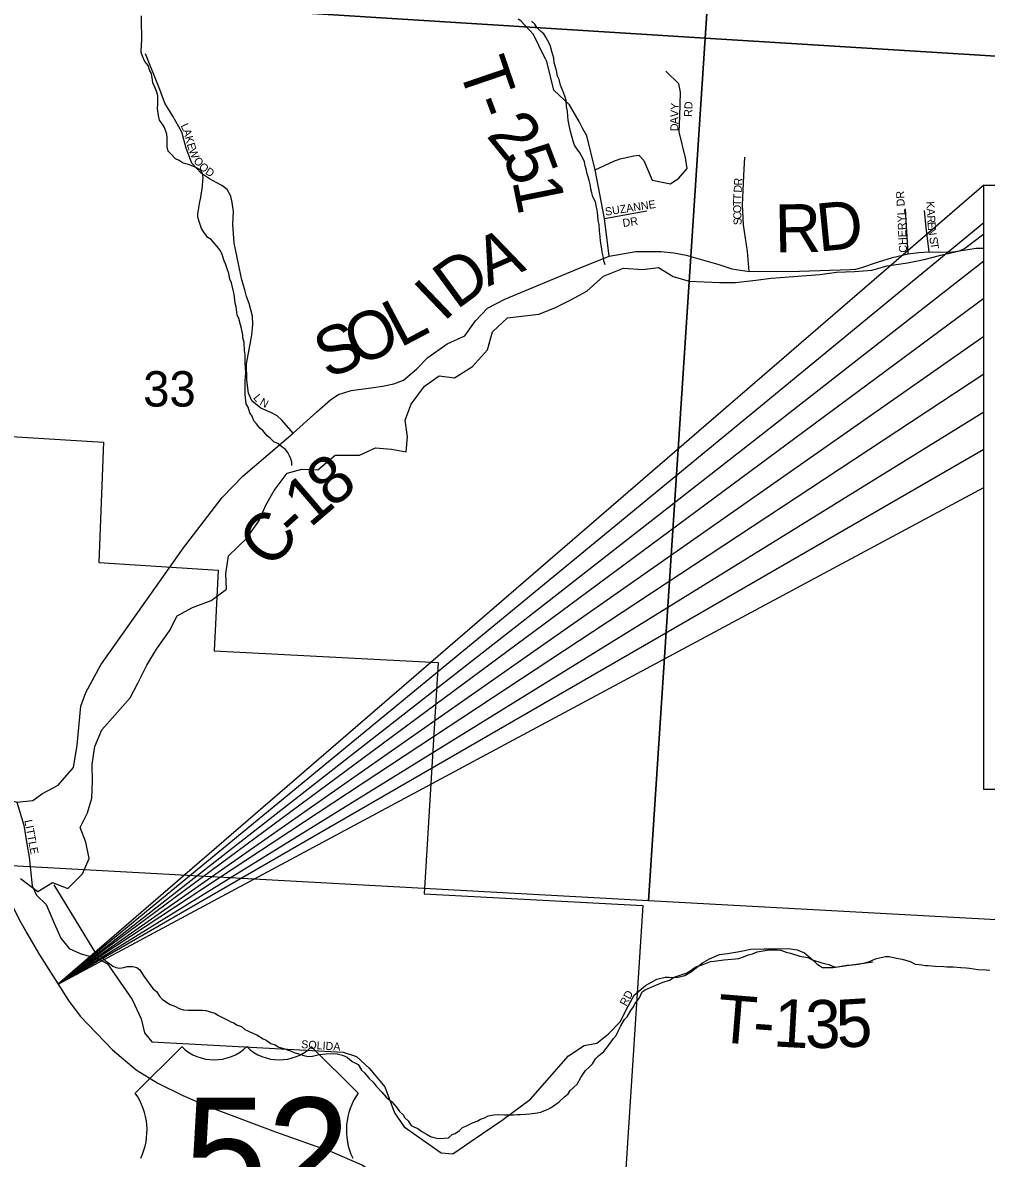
# Model space of a CAD drawing. Extents: x 0 to 34, y 0 to 22.
# Drawn here: x 4.916 to 6.056, y 15.623 to 16.966 of the extents above; entities that cross this region are included whole.
import ezdxf

# ---------------------------------------------------------------- set-up
doc = ezdxf.new("R2010")
doc.units = 0
for name, color, linetype in [('GM_X_City_Street', 7, 'Continuous'), ('GM_X_City_Street_Text', 7, 'Continuous'), ('GM_X_Corporation', 7, 'Continuous'), ('GM_X_County_Road', 7, 'Continuous'), ('GM_X_County_Road_Text', 7, 'Continuous'), ('GM_X_Minor_River', 7, 'Continuous'), ('GM_X_Section', 7, 'Continuous'), ('GM_X_Section_Text', 7, 'Continuous'), ('GM_X_Township_Road', 7, 'Continuous'), ('GM_X_Township_Road_Text', 7, 'Continuous'), ('GM_X_Township_Subdivision', 7, 'Continuous'), ('GM_X_Township_Subdivision_Text', 7, 'Continuous'), ('GM_X_US_Location', 7, 'Continuous'), ('GM_X_US_Route', 7, 'Continuous'), ('GM_X_US_Shield', 7, 'Continuous'), ('SH_Text', 7, 'Continuous')]:
    doc.layers.add(name, color=color, linetype=linetype)

msp = doc.modelspace()

# ---------------------------------------------------------------- linework, layer by layer
at = {"layer": 'GM_X_City_Street'}
for points in [[(4.7142, 16.2859), (4.7289, 16.2719), (4.7564, 16.2394), (4.784, 16.21), (4.7944, 16.1975), (4.7992, 16.1905), (4.8021, 16.1756), (4.8137, 16.1619), (4.8296, 16.149), (4.8455, 16.13), (4.8663, 16.0699), (4.8842, 16.0666), (4.8936, 16.0489), (4.909, 16.0441), (4.9279, 16.0462), (4.9395, 16.0544), (4.958, 16.0642), (4.9762, 16.0851), (4.9804, 16.1117), (4.9849, 16.1577), (4.9906, 16.174), (5.0084, 16.2067), (5.094, 16.3278), (5.0961, 16.3307)], [(4.909, 16.0441), (4.9172, 16.0171), (4.9208, 15.9949), (4.9237, 15.9791), (4.9251, 15.9641), (4.9273, 15.9454), (4.9323, 15.934), (4.9438, 15.9232), (4.9531, 15.901), (4.961, 15.8831), (4.971, 15.8709), (4.9839, 15.8651), (5.0054, 15.8587), (5.0162, 15.853), (5.0276, 15.8365), (5.0456, 15.8107), (5.0563, 15.7877), (5.06, 15.7711), (5.0686, 15.7607), (5.295, 15.7483), (5.3108, 15.7433), (5.3259, 15.7296), (5.3445, 15.7074), (5.356, 15.6766), (5.3675, 15.6601), (5.4111, 15.6292), (5.4248, 15.628), (5.4602, 15.6523), (5.4832, 15.6681), (5.517, 15.6927), (5.562, 15.7439), (5.5805, 15.7561), (5.5953, 15.7592), (5.6091, 15.7699), (5.6229, 15.7843), (5.6324, 15.8029), (5.6394, 15.8157), (5.6531, 15.8273), (5.6664, 15.8348), (5.6762, 15.8373), (5.6806, 15.8371)]]:
    msp.add_lwpolyline(points, dxfattribs=at)
at = {"layer": 'GM_X_Corporation'}
msp.add_lwpolyline([(4.6006, 16.4954), (5.0117, 16.4703), (5.0062, 16.3278), (5.1471, 16.3189), (5.1425, 16.2232), (5.4078, 16.2093), (5.3912, 15.9359), (5.65, 15.9221), (5.5944, 15.0667), (5.4633, 15.0824), (5.3998, 14.8756), (5.3493, 14.8892), (5.1229, 14.9601), (4.9836, 14.9934), (4.9409, 15.0109), (4.8087, 15.0697)], dxfattribs=at)
at = {"layer": 'GM_X_County_Road'}
for points in [[(5.6099, 16.6903), (5.6417, 16.6958), (5.6577, 16.6958), (5.6711, 16.6956), (5.6866, 16.694), (5.7011, 16.6914), (5.7397, 16.6804), (5.7552, 16.6752), (5.7755, 16.6719), (5.8351, 16.6725), (5.895, 16.6746), (5.9018, 16.675), (5.9089, 16.677), (5.9275, 16.683), (5.9453, 16.6887), (5.9638, 16.693), (5.9763, 16.6947), (5.9887, 16.6952), (6.0026, 16.695), (6.0167, 16.6954), (6.0244, 16.6964), (6.0304, 16.6993), (6.0532, 16.7167)], [(5.0961, 16.3307), (5.105, 16.3434), (5.152, 16.4048), (5.177, 16.4304), (5.2362, 16.4808), (5.2642, 16.5059), (5.2804, 16.5205), (5.2896, 16.5264), (5.3047, 16.5313), (5.3312, 16.5349), (5.3419, 16.5364), (5.3553, 16.5393), (5.3667, 16.5434), (5.3823, 16.5569), (5.3952, 16.5705), (5.4183, 16.5865), (5.4392, 16.596), (5.4517, 16.6138), (5.4661, 16.6286), (5.4865, 16.6393), (5.5735, 16.6756), (5.6099, 16.6903)]]:
    msp.add_lwpolyline(points, dxfattribs=at)
at = {"layer": 'GM_X_Minor_River'}
for points in [[(5.2344, 16.4426), (5.2345, 16.4464), (5.2334, 16.4506), (5.2316, 16.4541), (5.2298, 16.4579), (5.2268, 16.4614), (5.2227, 16.4645), (5.2178, 16.4684), (5.2133, 16.4707), (5.2089, 16.475), (5.2051, 16.4777), (5.2003, 16.4839), (5.1966, 16.4866), (5.1925, 16.492), (5.1895, 16.4954), (5.1873, 16.5008), (5.1848, 16.5047), (5.1826, 16.5115), (5.1804, 16.5154), (5.1791, 16.5264), (5.1794, 16.5431), (5.1798, 16.5469), (5.1799, 16.5534), (5.1796, 16.5572), (5.1794, 16.5644), (5.1791, 16.5686), (5.1792, 16.5739), (5.1785, 16.5785), (5.1779, 16.588), (5.1765, 16.5938), (5.1765, 16.5972), (5.1748, 16.6048), (5.1737, 16.609), (5.1719, 16.6166), (5.1697, 16.6209), (5.1684, 16.6304), (5.1673, 16.6346), (5.167, 16.638), (5.166, 16.6453), (5.165, 16.6502), (5.1632, 16.6586), (5.161, 16.6632), (5.16, 16.6697), (5.1578, 16.6751), (5.156, 16.6812), (5.1542, 16.6846), (5.1521, 16.6923), (5.1499, 16.6965), (5.1476, 16.6999), (5.1439, 16.7046), (5.1391, 16.71), (5.135, 16.7123), (5.1309, 16.7173), (5.1276, 16.7231), (5.1251, 16.73), (5.1233, 16.7365), (5.1233, 16.7403), (5.1242, 16.7475), (5.1255, 16.7547), (5.1267, 16.7596), (5.1272, 16.7634), (5.1284, 16.7695), (5.1289, 16.7744), (5.1293, 16.779), (5.1294, 16.7835), (5.1287, 16.7881), (5.1265, 16.7923), (5.1194, 16.7959), (5.1122, 16.7986), (5.1058, 16.8003), (5.101, 16.8034), (5.0968, 16.8054), (5.0913, 16.8112), (5.0879, 16.8143), (5.0869, 16.8196), (5.087, 16.8302), (5.0864, 16.8344), (5.0838, 16.8425), (5.0813, 16.8463), (5.0779, 16.8513), (5.0765, 16.8567), (5.0755, 16.865), (5.076, 16.8696), (5.0758, 16.8799), (5.0747, 16.8841), (5.0729, 16.8894), (5.07, 16.8952), (5.0697, 16.8986), (5.0683, 16.9062), (5.0665, 16.9097), (5.0643, 16.9158), (5.0606, 16.9204), (5.0577, 16.9269), (5.0562, 16.9312), (5.0564, 16.941), (5.0569, 16.9456), (5.057, 16.9551), (5.0564, 16.9608), (5.0566, 16.9745)], [(5.6053, 16.68), (5.6038, 16.6846), (5.6031, 16.6885), (5.6017, 16.6949), (5.6014, 16.6987), (5.6004, 16.7037), (5.5997, 16.7079), (5.5994, 16.7136), (5.5984, 16.7197), (5.5981, 16.7277), (5.5971, 16.7323), (5.5964, 16.7384), (5.5958, 16.7448), (5.5947, 16.7502), (5.5937, 16.7544), (5.5908, 16.7605), (5.5893, 16.7651), (5.5883, 16.7697), (5.5879, 16.7735), (5.5862, 16.7796), (5.5851, 16.7842), (5.584, 16.7876), (5.5826, 16.7934), (5.5815, 16.7972), (5.5809, 16.8018), (5.5794, 16.8056), (5.5772, 16.809), (5.5754, 16.8125), (5.572, 16.8167), (5.5691, 16.8217), (5.5673, 16.8263), (5.5644, 16.8378), (5.5627, 16.8454), (5.5616, 16.8511), (5.561, 16.8557), (5.5607, 16.8614), (5.5593, 16.8675), (5.559, 16.8748), (5.558, 16.8782), (5.5558, 16.8839), (5.554, 16.8885), (5.5525, 16.8924), (5.5507, 16.8992), (5.5489, 16.9031), (5.5475, 16.9099), (5.5465, 16.9138), (5.545, 16.9191), (5.5444, 16.9244), (5.5422, 16.9325), (5.5401, 16.9397), (5.5368, 16.9459), (5.535, 16.9493), (5.5327, 16.9532), (5.529, 16.9559), (5.5245, 16.9609), (5.522, 16.9647), (5.5182, 16.9682)], [(4.9987, 16.0689), (4.998, 16.0886), (5.0012, 16.1099), (5.0096, 16.1296), (5.0248, 16.147), (5.043, 16.1675), (5.0522, 16.1849), (5.0629, 16.2062), (5.0743, 16.2251), (5.0896, 16.2471), (5.0987, 16.2646), (5.117, 16.2744), (5.139, 16.2827), (5.1572, 16.2963), (5.1565, 16.3145), (5.1596, 16.3358), (5.1809, 16.3562), (5.1954, 16.3767), (5.2038, 16.3957), (5.2137, 16.4131), (5.229, 16.4336), (5.2464, 16.4381), (5.2653, 16.4373), (5.2858, 16.4547), (5.3146, 16.4546), (5.3336, 16.4636), (5.3525, 16.462), (5.3699, 16.4589), (5.3715, 16.4764), (5.3686, 16.4962), (5.3755, 16.5152), (5.3915, 16.5364), (5.4089, 16.5485), (5.4271, 16.5461), (5.4484, 16.5597), (5.4659, 16.5794), (5.472, 16.6007), (5.4895, 16.6174), (5.5266, 16.6218), (5.5456, 16.6293), (5.5646, 16.6384), (5.5835, 16.6489), (5.6033, 16.6664), (5.6268, 16.6762), (5.6495, 16.6746), (5.6685, 16.6768), (5.6859, 16.6661), (5.7048, 16.6607), (5.7222, 16.6598), (5.7404, 16.659), (5.7593, 16.659), (5.7836, 16.6619), (5.8017, 16.6641), (5.823, 16.6656), (5.8593, 16.6685), (5.879, 16.6714), (5.9002, 16.6721), (5.9207, 16.6736), (5.9389, 16.6788), (5.9631, 16.6825), (5.9829, 16.6863), (6.0026, 16.6915), (6.0246, 16.6967), (6.0443, 16.6997), (6.0532, 16.6997)], [(4.9134, 15.9537), (4.9338, 15.9384), (4.9513, 15.949), (4.9694, 15.9421), (4.9869, 15.9595), (4.9945, 15.9777), (4.9908, 15.9967), (4.9841, 16.0142), (4.9925, 16.0317), (4.9979, 16.0491), (4.9987, 16.0689)], [(4.9529, 15.9462), (5.0031, 15.8635), (5.0095, 15.8611), (5.0135, 15.8569), (5.0192, 15.853), (5.0225, 15.8503), (5.0263, 15.8487), (5.0308, 15.8478), (5.0357, 15.8485), (5.0396, 15.8496), (5.0464, 15.8499), (5.0509, 15.8486)], [(5.5577, 15.6958), (5.5616, 15.6991), (5.5639, 15.7029), (5.572, 15.7107), (5.5763, 15.7186), (5.5821, 15.7269), (5.5864, 15.7306), (5.5902, 15.7347), (5.5937, 15.7407), (5.5972, 15.7441), (5.6037, 15.7493), (5.6092, 15.7561), (5.615, 15.7647), (5.6181, 15.7681), (5.6208, 15.7733), (5.6236, 15.7794), (5.6283, 15.7869), (5.6314, 15.7903), (5.6356, 15.7978), (5.6388, 15.8019), (5.6403, 15.8057), (5.6458, 15.8128), (5.6489, 15.8196), (5.6527, 15.8222), (5.6631, 15.827), (5.6699, 15.8295), (5.6737, 15.8313), (5.6814, 15.8335), (5.6867, 15.8372), (5.6962, 15.8401), (5.7012, 15.8419), (5.7046, 15.8437), (5.7127, 15.8493), (5.7199, 15.8518), (5.7298, 15.8555), (5.7344, 15.8561), (5.7458, 15.8575), (5.7549, 15.8584), (5.7595, 15.8587), (5.7633, 15.8594), (5.7678, 15.8609), (5.7747, 15.8634), (5.7796, 15.8649), (5.785, 15.8671), (5.7945, 15.8688), (5.7998, 15.8695), (5.8043, 15.8694), (5.813, 15.8689), (5.8194, 15.8668), (5.8247, 15.8656), (5.8357, 15.862), (5.8451, 15.8603), (5.8496, 15.858), (5.8616, 15.854), (5.8662, 15.8531), (5.87, 15.8523), (5.8741, 15.8503), (5.8782, 15.8491), (5.8866, 15.8505), (5.8915, 15.8512), (5.898, 15.8518), (5.9052, 15.8525), (5.9143, 15.8546), (5.9181, 15.8557), (5.925, 15.859), (5.9299, 15.86), (5.9368, 15.8614), (5.9413, 15.8614), (5.95, 15.8597), (5.9568, 15.8584), (5.9662, 15.8556), (5.9722, 15.8525), (5.9764, 15.852), (5.9798, 15.8516), (5.984, 15.8511), (5.9874, 15.8511), (5.9957, 15.8502), (6.0059, 15.8496), (6.0097, 15.8492), (6.0169, 15.8494), (6.0263, 15.8485), (6.0324, 15.848), (6.0365, 15.8476), (6.0468, 15.8463), (6.0562, 15.8457), (6.0604, 15.8456)], [(5.0509, 15.8486), (5.0546, 15.8459), (5.0594, 15.8382), (5.0624, 15.834), (5.0676, 15.8267), (5.0705, 15.8232), (5.0743, 15.8201), (5.078, 15.8148), (5.0813, 15.8109), (5.0903, 15.8047), (5.0967, 15.8023), (5.1012, 15.7999), (5.1061, 15.7983), (5.1118, 15.7979), (5.119, 15.7981), (5.1227, 15.798), (5.1284, 15.798), (5.1326, 15.7975), (5.1367, 15.7967), (5.1435, 15.7947), (5.1476, 15.7916), (5.1533, 15.7892), (5.1578, 15.7868), (5.1623, 15.7841), (5.1657, 15.7833), (5.169, 15.7806), (5.1747, 15.7786), (5.1788, 15.7751), (5.1822, 15.7735), (5.1897, 15.77), (5.1931, 15.7691), (5.2006, 15.7641), (5.2039, 15.7625), (5.2096, 15.7586), (5.2148, 15.757), (5.2189, 15.7543), (5.225, 15.7526), (5.2291, 15.7511), (5.2329, 15.7499), (5.2381, 15.7475), (5.2453, 15.7455), (5.2487, 15.7446), (5.2536, 15.7434), (5.2589, 15.7437), (5.2669, 15.7455), (5.2749, 15.7465), (5.2806, 15.7468), (5.2881, 15.7466), (5.2945, 15.745), (5.2998, 15.7423), (5.3058, 15.7372), (5.3129, 15.7337), (5.317, 15.7272), (5.3203, 15.7241), (5.3255, 15.7175), (5.3307, 15.7129), (5.3344, 15.7083), (5.3411, 15.7009), (5.3459, 15.6952), (5.3527, 15.6897), (5.3582, 15.6835), (5.3619, 15.6782), (5.366, 15.6743), (5.3682, 15.6708), (5.3723, 15.667), (5.3757, 15.6616), (5.379, 15.66), (5.3836, 15.6581), (5.3884, 15.6545), (5.3944, 15.651), (5.3985, 15.6487), (5.4023, 15.6475), (5.4076, 15.6462), (5.4148, 15.6465), (5.4197, 15.6472), (5.424, 15.6509), (5.4278, 15.652), (5.4328, 15.6557), (5.4366, 15.6591), (5.4404, 15.6609), (5.4481, 15.6649), (5.4538, 15.6667), (5.4576, 15.669), (5.4626, 15.6708), (5.4668, 15.673), (5.4736, 15.6744), (5.4786, 15.6747), (5.4861, 15.6742), (5.4922, 15.6741), (5.4967, 15.6744), (5.5013, 15.6747), (5.5047, 15.6746), (5.5108, 15.6749), (5.5161, 15.6756), (5.5248, 15.6766), (5.529, 15.6773), (5.5328, 15.6791), (5.5378, 15.6809), (5.5412, 15.6831), (5.5508, 15.6898), (5.5577, 15.6958)]]:
    msp.add_lwpolyline(points, dxfattribs=at)
at = {"layer": 'GM_X_Section'}
for points in [[(5.7907, 17.959), (5.7237, 16.9481), (4.636, 17.0167), (4.6942, 18.026)], [(6.9079, 17.8893), (6.8455, 16.8788), (5.7237, 16.9481), (5.7907, 17.959)], [(4.636, 17.0167), (5.7237, 16.9481), (5.6567, 15.9275), (4.5788, 15.9866)]]:
    msp.add_lwpolyline(points, close=True, dxfattribs=at)
msp.add_lwpolyline([(6.795, 16.0591), (6.7831, 15.8661), (5.6567, 15.9275), (5.7237, 16.9481), (6.8455, 16.8788), (6.8391, 16.7743)], dxfattribs=at)
at = {"layer": 'GM_X_Township_Road'}
for points in [[(5.5345, 16.9238), (5.5332, 16.9265), (5.5203, 16.9524), (5.5055, 16.9688), (5.5022, 16.9708)], [(5.579, 16.8409), (5.5743, 16.8496), (5.5629, 16.8694), (5.5445, 16.8867), (5.5362, 16.9205), (5.5345, 16.9238)], [(5.6099, 16.6903), (5.6046, 16.7348), (5.5934, 16.7923), (5.5835, 16.8325), (5.579, 16.8409)], [(5.6806, 15.8371), (5.6902, 15.8367), (5.6995, 15.8393), (5.7073, 15.8439), (5.7206, 15.8541), (5.7286, 15.8588), (5.7404, 15.8641), (5.7502, 15.8652), (5.7644, 15.8675), (5.7777, 15.8703), (5.7934, 15.8706), (5.809, 15.8708), (5.8219, 15.8712), (5.8323, 15.8696), (5.8412, 15.8661), (5.8496, 15.8588), (5.8561, 15.8524), (5.8623, 15.8486), (5.8745, 15.8484), (5.9219, 15.8551)]]:
    msp.add_lwpolyline(points, dxfattribs=at)
at = {"layer": 'GM_X_Township_Subdivision'}
for points in [[(5.1749, 16.6635), (5.1748, 16.6639), (5.1712, 16.6812), (5.166, 16.7055), (5.1648, 16.728), (5.1654, 16.7431), (5.1638, 16.7538), (5.1623, 16.7614), (5.1578, 16.769), (5.1517, 16.7739), (5.1456, 16.777), (5.1369, 16.7819), (5.1274, 16.788), (5.116, 16.8001), (5.1092, 16.818), (5.1042, 16.837), (5.0936, 16.8557), (5.084, 16.8714), (5.0781, 16.8875), (5.0613, 16.9297)], [(5.6266, 16.8062), (5.6392, 16.8088), (5.6449, 16.8097), (5.651, 16.8036), (5.6608, 16.7801), (5.6824, 16.7758), (5.6923, 16.7826), (5.7023, 16.7939), (5.7004, 16.8065), (5.6927, 16.8373), (5.6936, 16.8555), (5.6945, 16.8841), (5.6923, 16.8943), (5.6769, 16.9093)], [(5.5934, 16.7923), (5.6154, 16.8025), (5.6231, 16.8055), (5.6266, 16.8062)], [(5.7755, 16.6719), (5.7735, 16.6958), (5.7689, 16.7273), (5.7677, 16.7505), (5.7694, 16.7855), (5.7707, 16.8075)], [(5.6046, 16.7348), (5.6546, 16.744)], [(5.9638, 16.693), (5.9608, 16.7462)], [(5.9887, 16.6952), (5.9851, 16.7243), (5.9832, 16.7443)], [(5.2362, 16.4808), (5.2226, 16.4961), (5.2172, 16.5013), (5.2095, 16.5054), (5.1977, 16.5103), (5.1872, 16.519), (5.1831, 16.5282), (5.1811, 16.5434), (5.1806, 16.5629), (5.187, 16.5967), (5.1883, 16.6095), (5.1878, 16.6194), (5.184, 16.6341), (5.1807, 16.6427), (5.1789, 16.6504), (5.1749, 16.6635)]]:
    msp.add_lwpolyline(points, dxfattribs=at)
at = {"layer": 'GM_X_US_Route'}
for points in [[(4.8309, 16.0512), (4.8399, 16.0369), (4.8834, 15.9611), (4.9139, 15.9017), (4.9358, 15.8635), (4.9701, 15.8096), (4.9839, 15.791), (5.0221, 15.7512), (5.0502, 15.7273), (5.0757, 15.7119), (5.1054, 15.697), (5.1373, 15.6832), (5.2153, 15.654), (5.2817, 15.6306), (5.3172, 15.6152), (5.3507, 15.5945), (5.4554, 15.4954), (5.5676, 15.398), (5.6488, 15.3249)], [(4.9139, 15.9017), (4.921, 15.8893), (4.9358, 15.8635), (4.9579, 15.8288)]]:
    msp.add_lwpolyline(points, dxfattribs=at)
at = {"layer": 'GM_X_US_Shield'}
for p, q in [((5.1041, 15.7549), (5.0492, 15.7)), ((5.3129, 15.7), (5.2579, 15.7549))]:
    msp.add_line(p, q, dxfattribs=at)
for centre, radius, start, end in [((5.1426, 15.7942), 0.0549, 225.573, 314.427), ((5.2195, 15.7942), 0.0549, 225.573, 314.427), ((4.9862, 15.6559), 0.0769, 334.5471, 35.0009), ((5.3759, 15.6559), 0.0769, 144.9991, 205.4529)]:
    msp.add_arc(centre, radius, start, end, dxfattribs=at)
at = {"layer": 'SH_Text'}
msp.add_line((6.0532, 16.4614), (4.9579, 15.8288), dxfattribs=at)
for points in [[(6.0532, 16.7743), (4.9579, 15.8288), (6.0532, 16.4167)], [(6.0532, 16.7296), (4.9579, 15.8288), (6.0532, 16.6849)], [(6.0532, 16.6402), (4.9579, 15.8288), (6.0532, 16.5955)], [(6.0532, 16.5508), (4.9579, 15.8288), (6.0532, 16.5061)]]:
    msp.add_lwpolyline(points, dxfattribs=at)
msp.add_lwpolyline([(6.0532, 16.7743), (7.8426, 16.7743), (7.8426, 16.0591), (6.0532, 16.0591)], close=True, dxfattribs=at)

# ---------------------------------------------------------------- texts
at = {"layer": 'GM_X_City_Street_Text'}
for s, rotation, p in [('LITTLE', 280.8384, (4.9178, 16.0225)), ('RD', 62.114, (5.6303, 15.8021)), ('SOLIDA', 356.1861, (5.2453, 15.7532))]:
    msp.add_text(s, height=0.00947, rotation=rotation, dxfattribs=at).set_placement(p)
at = {"layer": 'GM_X_County_Road_Text'}
for s, rotation, p in [('D', 5.6492, (5.858, 16.6955)), ('R', 0.8443, (5.8063, 16.6946)), ('A', 23.6227, (5.4668, 16.654)), ('D', 36.2524, (5.4293, 16.6261)), ('I', 43.7313, (5.414, 16.6113)), ('L', 27.9642, (5.3626, 16.5814)), ('O', 23.0796, (5.3119, 16.5595)), ('S', 22.9889, (5.2765, 16.5445)), ('8', 40.3495, (5.2824, 16.3906)), ('1', 40.6202, (5.2559, 16.3679)), ('C', 50.205, (5.2104, 16.3182)), ('-', 41.8567, (5.2387, 16.3525))]:
    msp.add_text(s, height=0.0568, rotation=rotation, dxfattribs=at).set_placement(p)
at = {"layer": 'GM_X_Section_Text'}
msp.add_text('33', height=0.04186, rotation=0, dxfattribs=at).set_placement((5.0585, 16.5123))
at = {"layer": 'GM_X_Township_Road_Text'}
for s, rotation, p in [('T', 288.8339, (5.431, 16.9139)), ('-', 290.6471, (5.4453, 16.8719)), ('2', 309.2786, (5.4636, 16.8327)), ('5', 290.818, (5.4833, 16.8097)), ('1', 281.4519, (5.4951, 16.7794)), ('T', 355.3396, (5.7361, 15.7606)), ('1', 356.8641, (5.8033, 15.7553)), ('3', 0.0586, (5.8417, 15.7533)), ('5', 3.3701, (5.8803, 15.7534)), ('-', 355.6943, (5.7788, 15.7571))]:
    msp.add_text(s, height=0.0568, rotation=rotation, dxfattribs=at).set_placement(p)
at = {"layer": 'GM_X_Township_Subdivision_Text'}
for s, rotation, p in [('V', 87.7044, (5.6918, 16.8546)), ('Y', 87.0043, (5.6921, 16.8629)), ('RD', 87.1392, (5.7079, 16.8548)), ('A', 89.6503, (5.6918, 16.8464)), ('L', 294.45, (5.1026, 16.8448)), ('A', 287.952, (5.1053, 16.839)), ('D', 89.9563, (5.6918, 16.8381)), ('K', 284.8536, (5.1078, 16.8312)), ('E', 287.2066, (5.11, 16.8227)), ('W', 291.0246, (5.1122, 16.8157)), ('O', 306.658, (5.1175, 16.8031)), ('O', 316.1942, (5.1236, 16.7951)), ('D', 327.5983, (5.1312, 16.7881)), ('R', 87.1331, (5.7671, 16.7736)), ('D', 87.1355, (5.7667, 16.7652)), ('SUZANNE', 8.8802, (5.6058, 16.7381)), ('T', 88.5518, (5.766, 16.7495)), ('T', 87.2396, (5.7662, 16.7561)), ('CHERYL DR', 92.9341, (5.9626, 16.6946)), ('O', 91.5083, (5.7663, 16.7413)), ('C', 91.9918, (5.7665, 16.7338)), ('K', 273.1489, (5.9853, 16.7548)), ('A', 273.1489, (5.9858, 16.7465)), ('DR', 8.974, (5.6266, 16.7247)), ('S', 91.9948, (5.7668, 16.7272)), ('R', 273.1344, (5.9862, 16.7382)), ('E', 274.2654, (5.9867, 16.7305)), ('N', 277.8822, (5.9872, 16.7232)), ('S', 278.6102, (5.9888, 16.7123)), ('T', 278.6145, (5.9898, 16.7057)), ('L', 309.684, (5.1883, 16.5223)), ('N', 331.5598, (5.1956, 16.5147))]:
    msp.add_text(s, height=0.00947, rotation=rotation, dxfattribs=at).set_placement(p)
at = {"layer": 'GM_X_US_Location'}
for s in ['0', '/']:
    msp.add_text(s, height=0.000189, dxfattribs=at).set_placement((5.181, 15.6275))
at = {"layer": 'GM_X_US_Shield'}
msp.add_text('52', height=0.13184, dxfattribs=at).set_placement((5.1072, 15.5627))

doc.saveas('drawing.dxf')
